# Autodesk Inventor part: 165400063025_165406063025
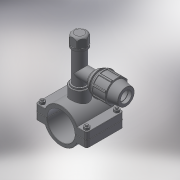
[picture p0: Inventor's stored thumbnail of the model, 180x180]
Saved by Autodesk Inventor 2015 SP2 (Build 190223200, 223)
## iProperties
Created: 2017-05
Part Number: 165400063025_165406063025
Material: Generic
Description: PLASSON TAPPER FOR PE+PVC PIPE 63-25
Document SubType Name: Modeling
Designer: KIM
Density: 1 g/cm^3
Appearance: Default
Author: KIM
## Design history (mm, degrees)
derived "16540.ipt"
feature "Solid1::16540.ipt"
feature "Solid2::16540.ipt"
tag "TaggingFeature1"
body "Solid1"
other parameters: "d0" = 78.75, "d1" = 116, "d2" = 31.5, "d3" = 63, "d4" = 84, "d5" = 0, "d6" = 5.8, "d7" = 116, "d8" = 0.1, "d10" = 0, "d11" = 0.63, "d14" = 39.3783, "d20" = 0.63, "d23" = 0.63, "d37" = 8, "d38" = 39.5, "d39" = 0, "d40" = 3, "d41" = 5, "d42" = 0, "d43" = 6, "d44" = 3, "d45" = 0, "d46" = 0.63, "d51" = 61, "d52" = 30.291, "d53" = 21, "d54" = 0, "d55" = 25, "d57" = 0, "d58" = 68.04, "d60" = 0, "d63" = 8, "d66" = 68, "d67" = 25, "d68" = 8.75, "d69" = 21, "d70" = 54, "d71" = 40.5, "d72" = 1.5, "d73" = 43.2, "d74" = 120 deg, "d75" = 37.5, "d76" = 10 deg, "d77" = 48.6, "d78" = 31.5, "d79" = 61, "d81" = 105, "d82" = 6.1, "d87" = 15, "d90" = 50.22, "d91" = 35 deg, "d92" = 17.5 deg, "d94" = 0, "d96" = 360 deg, "d98" = 0.5, "d99" = 67.1, "d100" = 27.2619, "d101" = 135 deg, "d102" = 1.08, "d105" = 2.7, "d106" = 0, "d107" = 0.1, "d108" = 27.2619, "d109" = 33.3201, "d111" = 26, "d112" = 6.5, "d113" = 3.5, "d116" = 0, "d118" = 21, "d119" = 0, "d122" = 57, "d_" = 63, "B_" = 25, "G_" = 30.291, "A_" = 61, "L_" = 116, "L_1" = 84, "l_2" = 21, "d_1" = 25, "E_" = 54, "l_" = 61, "H_" = 105, "H_1" = 57
